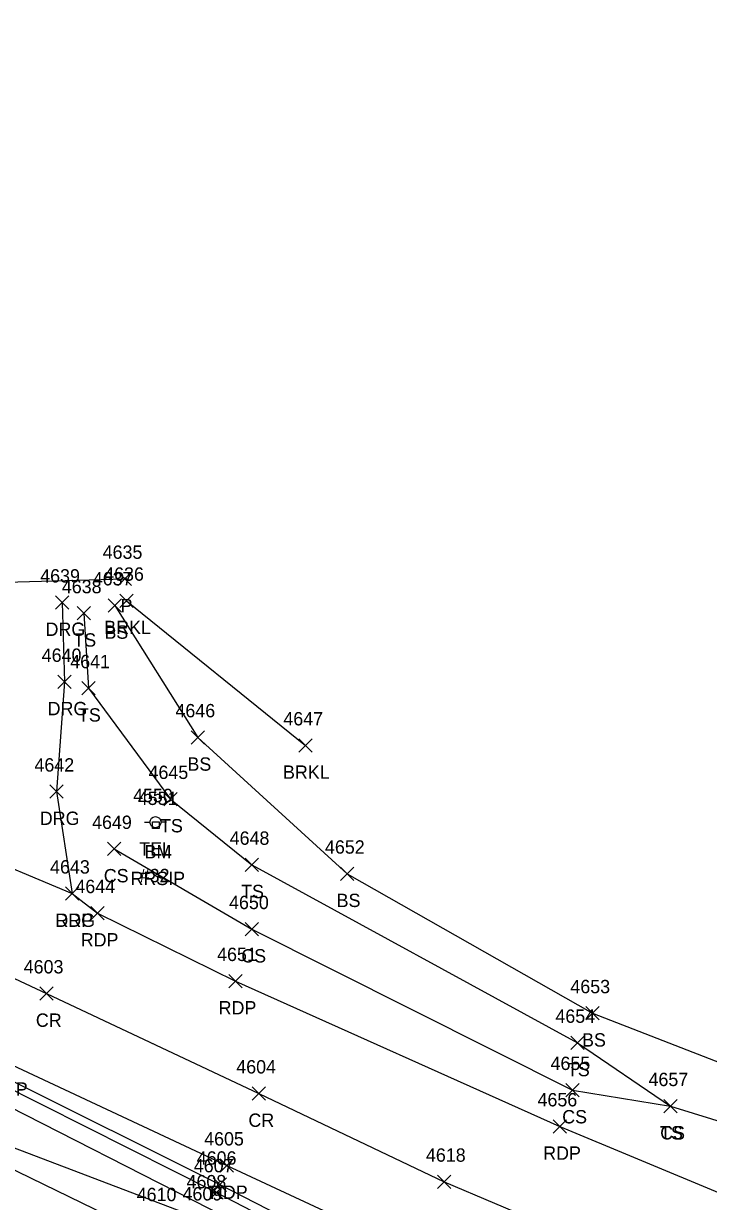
# Model space of a CAD drawing. Extents: x 1611797 to 1633212, y 298978 to 305475.
# Drawn here: x 1619703.4 to 1619805.9, y 301313.3 to 301489.8 of the extents above; entities that cross this region are included whole.
import ezdxf

# ---------------------------------------------------------------- set-up
doc = ezdxf.new("R2010")
doc.units = 0
for name, color, linetype in [('C_A', 7, 'Continuous'), ('C_C', 7, 'Continuous'), ('C_I', 7, 'Continuous'), ('CPBM', 7, 'Continuous'), ('D_A', 7, 'Continuous'), ('D_I', 7, 'Continuous'), ('D_TIC', 7, 'Continuous'), ('DCP', 7, 'Continuous'), ('L_A', 7, 'Continuous'), ('L_I', 7, 'Continuous'), ('L_TIC', 7, 'Continuous'), ('LAWA', 7, 'Continuous'), ('LAWE', 7, 'Continuous'), ('LELB', 7, 'Continuous'), ('M_I', 7, 'Continuous'), ('P_A', 7, 'Continuous'), ('P_I', 7, 'Continuous'), ('P_TIC', 7, 'Continuous'), ('PET', 7, 'Continuous'), ('PRC', 7, 'Continuous'), ('R_A', 7, 'Continuous'), ('R_I', 7, 'Continuous'), ('R_TIC', 7, 'Continuous'), ('RDG', 7, 'Continuous'), ('U_A', 7, 'Continuous'), ('U_C', 7, 'Continuous'), ('U_I', 7, 'Continuous'), ('UP', 7, 'Continuous')]:
    doc.layers.add(name, color=color, linetype=linetype)

msp = doc.modelspace()

# ---------------------------------------------------------------- linework, layer by layer
at = {"layer": 'CPBM'}
for p, q in [((1619722.68, 301369.21), (1619722.68, 301370.21)), ((1619722.68, 301370.21), (1619723.68, 301370.21)), ((1619723.68, 301370.21), (1619723.68, 301369.21)), ((1619723.68, 301369.21), (1619722.68, 301369.21)), ((1619723.18, 301369.71), (1619723.18, 301369.71)), ((1619723.18, 301369.71), (1619723.18, 301369.71))]:
    msp.add_line(p, q, dxfattribs=at)
at = {"layer": 'D_TIC'}
for points in [[(1619717.54, 301405.6), (1619719.54, 301407.6)], [(1619719.54, 301405.6), (1619717.54, 301407.6)]]:
    msp.add_lwpolyline(points, dxfattribs=at)
at = {"layer": 'DCP'}
msp.add_lwpolyline([(1619688.22, 301405.73), (1619718.54, 301406.6)], dxfattribs=at)
at = {"layer": 'L_TIC'}
for points in [[(1619716.05, 301401.62), (1619718.05, 301403.62)], [(1619718.05, 301401.62), (1619716.05, 301403.62)], [(1619717.82, 301402.32), (1619719.82, 301404.32)], [(1619719.82, 301402.32), (1619717.82, 301404.32)], [(1619711.43, 301400.44), (1619713.43, 301402.44)], [(1619713.43, 301400.44), (1619711.43, 301402.44)], [(1619712.12, 301389.21), (1619714.12, 301391.21)], [(1619714.12, 301389.21), (1619712.12, 301391.21)], [(1619728.49, 301381.85), (1619730.49, 301383.85)], [(1619730.49, 301381.85), (1619728.49, 301383.85)], [(1619744.59, 301380.64), (1619746.59, 301382.64)], [(1619746.59, 301380.64), (1619744.59, 301382.64)], [(1619724.41, 301372.61), (1619726.41, 301374.61)], [(1619726.41, 301372.61), (1619724.41, 301374.61)], [(1619715.96, 301365.12), (1619717.96, 301367.12)], [(1619717.96, 301365.12), (1619715.96, 301367.12)], [(1619736.56, 301362.75), (1619738.56, 301364.75)], [(1619738.56, 301362.75), (1619736.56, 301364.75)], [(1619750.83, 301361.42), (1619752.83, 301363.42)], [(1619752.83, 301361.42), (1619750.83, 301363.42)], [(1619736.55, 301353.11), (1619738.55, 301355.11)], [(1619738.55, 301353.11), (1619736.55, 301355.11)], [(1619787.58, 301340.51), (1619789.58, 301342.51)], [(1619789.58, 301340.51), (1619787.58, 301342.51)], [(1619785.34, 301336.07), (1619787.34, 301338.07)], [(1619787.34, 301336.07), (1619785.34, 301338.07)], [(1619784.6, 301329), (1619786.6, 301331)], [(1619786.6, 301329), (1619784.6, 301331)], [(1619799.28, 301326.59), (1619801.28, 301328.59)], [(1619801.28, 301326.59), (1619799.28, 301328.59)], [(1619799.28, 301326.59), (1619801.28, 301328.59)], [(1619801.28, 301326.59), (1619799.28, 301328.59)], [(1619731.26, 301313.67), (1619733.26, 301315.67)], [(1619733.26, 301313.67), (1619731.26, 301315.67)], [(1619731.76, 301314.82), (1619733.76, 301316.82)], [(1619733.76, 301314.82), (1619731.76, 301316.82)]]:
    msp.add_lwpolyline(points, dxfattribs=at)
at = {"layer": 'LAWA'}
msp.add_lwpolyline([(1619507.86, 301398.95), (1619518.08, 301400.79), (1619556.65, 301387.52), (1619583.35, 301368.71), (1619617.87, 301352.68), (1619658.72, 301335.08), (1619694.86, 301321.5), (1619725.46, 301306.6), (1619750.78, 301288.01), (1619784.9, 301274.32), (1619812.4, 301257.15), (1619844.1, 301250.77), (1619874.95, 301250.41), (1619914.22, 301239.23), (1619945.35, 301230.93), (1619986.13, 301221.13), (1620021.48, 301214.73), (1620067.45, 301208.49), (1620101.58, 301197.67), (1620125.21, 301192.85)], dxfattribs=at)
at = {"layer": 'LAWE'}
msp.add_lwpolyline([(1619718.82, 301403.32), (1619745.59, 301381.64)], dxfattribs=at)
at = {"layer": 'LELB'}
for points in [[(1619350.31, 301489.81), (1619380.89, 301476.99), (1619406.21, 301465.78), (1619425.96, 301458.32), (1619457.01, 301443.93), (1619488.18, 301429.04), (1619515.79, 301415.84), (1619523.25, 301412.34), (1619557.22, 301396.43), (1619595.64, 301379.74), (1619625.49, 301366.11), (1619664.9, 301348.53), (1619700.1, 301332.19), (1619732.76, 301315.82), (1619759.48, 301302.13), (1619789.83, 301287.62), (1619820.2, 301275.83), (1619850.42, 301266.87), (1619878.56, 301257.32), (1619912.05, 301251.69), (1619947.78, 301244.54), (1619986.64, 301235.92)], [(1619515.86, 301413.84), (1619522.39, 301411.67), (1619557.04, 301395.57), (1619595.01, 301378.34), (1619625.28, 301365.19), (1619664.7, 301347.42), (1619699.56, 301331.11), (1619732.26, 301314.67), (1619758.81, 301300.85), (1619789.23, 301285.42), (1619819.18, 301274.31), (1619849.56, 301265.07), (1619878.74, 301254.24), (1619911.39, 301248.67), (1619947.63, 301242.31), (1619986.12, 301232.79)], [(1619514.13, 301412.04), (1619521.16, 301409.66), (1619556.07, 301393.79), (1619593.93, 301376.98), (1619624.81, 301363.73), (1619664.19, 301346.3), (1619698.66, 301328.84), (1619731.18, 301312.27), (1619757.56, 301299.07), (1619788.59, 301282.92), (1619818.22, 301271.64), (1619848.03, 301261.72), (1619876.44, 301251.78), (1619910.7, 301243.48), (1619946.63, 301234.74), (1619971.5, 301227.31), (1619985.16, 301225.14), (1620021.48, 301214.73)], [(1619717.05, 301402.62), (1619729.49, 301382.85), (1619751.83, 301362.42), (1619788.58, 301341.51), (1619840.33, 301321.37), (1619859.82, 301312.4), (1619885.93, 301308.98), (1619917.76, 301301.6), (1619954.63, 301284.39), (1619995.46, 301278.81), (1620037.59, 301270.1), (1620080.58, 301262.9), (1620111.05, 301256.31), (1620134.36, 301250.9), (1620155.92, 301243.69), (1620184.2, 301240.01), (1620186.37, 301239.29), (1620187.23, 301238.52), (1620209.89, 301239.08), (1620216.8, 301243.54), (1620236.7, 301237.64)], [(1619712.43, 301401.44), (1619713.12, 301390.21), (1619725.41, 301373.61), (1619737.56, 301363.75), (1619786.34, 301337.07), (1619800.28, 301327.59), (1619837.75, 301316), (1619857.62, 301306.82), (1619872.16, 301301.99), (1619887.37, 301302.9), (1619915.15, 301296.19), (1619953.85, 301281.7), (1619995.44, 301273.48), (1620035.7, 301263.81), (1620079.78, 301255.69), (1620110.34, 301250.13), (1620133.61, 301245.85), (1620185.9, 301234.31), (1620209.46, 301228.92), (1620249.02, 301218.59), (1620282.74, 301209.51), (1620314.25, 301201.24), (1620350.31, 301189.61), (1620412.81, 301166.44)], [(1619716.96, 301366.12), (1619737.55, 301354.11), (1619785.6, 301330), (1619800.28, 301327.59)], [(1619685.12, 301328.75), (1619696.06, 301323.61), (1619730.59, 301310.45), (1619756.56, 301297.34), (1619787.5, 301280.33), (1619817.39, 301268.62), (1619845.61, 301256.67), (1619874.95, 301250.41)]]:
    msp.add_lwpolyline(points, dxfattribs=at)
at = {"layer": 'P_TIC'}
for points in [[(1619709.67, 301358.44), (1619711.67, 301360.44)], [(1619711.67, 301358.44), (1619709.67, 301360.44)], [(1619713.46, 301355.51), (1619715.46, 301357.51)], [(1619715.46, 301355.51), (1619713.46, 301357.51)], [(1619734.11, 301345.33), (1619736.11, 301347.33)], [(1619736.11, 301345.33), (1619734.11, 301347.33)], [(1619705.8, 301343.47), (1619707.8, 301345.47)], [(1619707.8, 301343.47), (1619705.8, 301345.47)], [(1619737.62, 301328.48), (1619739.62, 301330.48)], [(1619739.62, 301328.48), (1619737.62, 301330.48)], [(1619782.71, 301323.55), (1619784.71, 301325.55)], [(1619784.71, 301323.55), (1619782.71, 301325.55)], [(1619732.81, 301317.69), (1619734.81, 301319.69)], [(1619734.81, 301317.69), (1619732.81, 301319.69)], [(1619765.38, 301315.26), (1619767.38, 301317.26)], [(1619767.38, 301315.26), (1619765.38, 301317.26)]]:
    msp.add_lwpolyline(points, dxfattribs=at)
at = {"layer": 'PET'}
for points in [[(1619561.18, 301427.13), (1619589.22, 301414.46), (1619621.64, 301399.56), (1619645.53, 301388.44), (1619676.08, 301374.23), (1619678.71, 301373.41), (1619694.71, 301366.12), (1619710.67, 301359.44), (1619714.46, 301356.51), (1619735.11, 301346.33), (1619783.71, 301324.55), (1619832.02, 301304.42), (1619849.55, 301298.27), (1619870.41, 301291.84), (1619910.7, 301281.21), (1619950.83, 301272.88), (1619994.49, 301265.52)], [(1619558.04, 301399.85), (1619596.27, 301382.3), (1619626.79, 301368.76), (1619665.72, 301350.73), (1619700.87, 301334.15), (1619733.81, 301318.69), (1619761.36, 301305.85), (1619791.6, 301292.8), (1619823.48, 301280.05), (1619851.63, 301270.31), (1619880.36, 301262.32), (1619912.48, 301254.3), (1619949.02, 301246.88), (1619987.97, 301240.43)]]:
    msp.add_lwpolyline(points, dxfattribs=at)
at = {"layer": 'PRC'}
msp.add_lwpolyline([(1619561.88, 301411.99), (1619599.81, 301394.69), (1619632.15, 301379.47), (1619669.86, 301361.78), (1619706.8, 301344.47), (1619738.62, 301329.48), (1619766.38, 301316.26), (1619796.53, 301303.45), (1619827.59, 301291.15), (1619854.63, 301281.96), (1619882.39, 301274.22), (1619915.66, 301266.28), (1619950.93, 301259.45), (1619990.95, 301252.78)], dxfattribs=at)
at = {"layer": 'R_TIC'}
for points in [[(1619708.19, 301402.05), (1619710.19, 301404.05)], [(1619710.19, 301402.05), (1619708.19, 301404.05)], [(1619708.5, 301390.16), (1619710.5, 301392.16)], [(1619710.5, 301390.16), (1619708.5, 301392.16)], [(1619707.33, 301373.72), (1619709.33, 301375.72)], [(1619709.33, 301373.72), (1619707.33, 301375.72)], [(1619709.67, 301358.44), (1619711.67, 301360.44)], [(1619711.67, 301358.44), (1619709.67, 301360.44)]]:
    msp.add_lwpolyline(points, dxfattribs=at)
at = {"layer": 'RDG'}
msp.add_lwpolyline([(1619709.19, 301403.05), (1619709.5, 301391.16), (1619708.33, 301374.72), (1619710.67, 301359.44)], dxfattribs=at)
at = {"layer": 'UP'}
for p, q in [((1619721.48, 301370.13), (1619722.3, 301370.13)), ((1619723.14, 301370.14), (1619723.14, 301370.14)), ((1619724.8, 301370.14), (1619723.97, 301370.14)), ((1619723.97, 301370.14), (1619723.97, 301370.14)), ((1619724.8, 301370.14), (1619724.8, 301370.14))]:
    msp.add_line(p, q, dxfattribs=at)
msp.add_circle((1619723.14, 301370.14), 0.833, dxfattribs=at)

# ---------------------------------------------------------------- texts
at = {"layer": 'C_A'}
msp.add_text('BM', height=2, dxfattribs=at).set_placement((1619721.5, 301364.71))
at = {"layer": 'C_C'}
msp.add_text('RRSIP', height=2, dxfattribs=at).set_placement((1619719.4, 301360.71))
at = {"layer": 'C_I'}
msp.add_text('4551', height=2, dxfattribs=at).set_placement((1619720.49, 301372.71))
at = {"layer": 'D_A'}
msp.add_text('P', height=2, dxfattribs=at).set_placement((1619717.91, 301401.6))
at = {"layer": 'D_I'}
msp.add_text('4635', height=2, dxfattribs=at).set_placement((1619715.23, 301409.6))
at = {"layer": 'L_A'}
for s, p in [('BRKL', (1619715.47, 301398.32)), ('TS', (1619710.84, 301396.44)), ('BS', (1619715.49, 301397.62)), ('TS', (1619711.53, 301385.21)), ('BS', (1619727.93, 301377.85)), ('BRKL', (1619742.24, 301376.64)), ('TS', (1619723.82, 301368.61)), ('CS', (1619715.4, 301361.12)), ('TS', (1619735.97, 301358.75)), ('BS', (1619750.27, 301357.42)), ('CS', (1619735.99, 301349.11)), ('BS', (1619787.02, 301336.51)), ('TS', (1619784.75, 301332.07)), ('CS', (1619784.05, 301325)), ('TS', (1619798.69, 301322.59)), ('CS', (1619798.72, 301322.59))]:
    msp.add_text(s, height=2, dxfattribs=at).set_placement(p)
at = {"layer": 'L_I'}
for s, p in [('4637', (1619713.75, 301405.62)), ('4636', (1619715.46, 301406.32)), ('4638', (1619709.12, 301404.44)), ('4641', (1619710.38, 301393.21)), ('4646', (1619726.13, 301385.85)), ('4647', (1619742.29, 301384.64)), ('4645', (1619722.1, 301376.61)), ('4649', (1619713.65, 301369.12)), ('4648', (1619734.25, 301366.75)), ('4652', (1619748.52, 301365.42)), ('4650', (1619734.16, 301357.11)), ('4653', (1619785.27, 301344.51)), ('4654', (1619783.03, 301340.07)), ('4655', (1619782.3, 301333)), ('4657', (1619796.97, 301330.59)), ('4657', (1619796.97, 301330.59)), ('4606', (1619729.32, 301318.82)), ('4607', (1619728.88, 301317.67)), ('4608', (1619727.79, 301315.27)), ('4609', (1619727.19, 301313.45))]:
    msp.add_text(s, height=2, dxfattribs=at).set_placement(p)
at = {"layer": 'M_I'}
msp.add_text('4610', height=2, dxfattribs=at).set_placement((1619720.33, 301313.35))
at = {"layer": 'P_A'}
for s, p in [('RDP', (1619708.15, 301354.44)), ('RDP', (1619711.95, 301351.51)), ('RDP', (1619732.6, 301341.33)), ('CR', (1619705.23, 301339.47)), ('RDP', (1619698.36, 301329.15)), ('CR', (1619737.06, 301324.48)), ('RDP', (1619781.2, 301319.55)), ('RDP', (1619731.3, 301313.69))]:
    msp.add_text(s, height=2, dxfattribs=at).set_placement(p)
at = {"layer": 'P_I'}
for s, p in [('4643', (1619707.36, 301362.44)), ('4644', (1619711.15, 301359.51)), ('4651', (1619732.37, 301349.33)), ('4603', (1619703.41, 301347.47)), ('4604', (1619735.24, 301332.48)), ('4656', (1619780.35, 301327.55)), ('4605', (1619730.43, 301321.69)), ('4618', (1619763.64, 301319.26))]:
    msp.add_text(s, height=2, dxfattribs=at).set_placement(p)
at = {"layer": 'R_A'}
for p in [(1619706.68, 301398.05), (1619706.99, 301386.16), (1619705.82, 301369.72), (1619708.15, 301354.44)]:
    msp.add_text('DRG', height=2, dxfattribs=at).set_placement(p)
at = {"layer": 'R_I'}
for s, p in [('4639', (1619705.88, 301406.05)), ('4640', (1619706.11, 301394.16)), ('4642', (1619705.02, 301377.72)), ('4643', (1619707.36, 301362.44))]:
    msp.add_text(s, height=2, dxfattribs=at).set_placement(p)
at = {"layer": 'U_A'}
msp.add_text('TEL', height=2, dxfattribs=at).set_placement((1619720.7, 301365.14))
at = {"layer": 'U_C'}
msp.add_text('#32', height=2, dxfattribs=at).set_placement((1619720.78, 301361.14))
at = {"layer": 'U_I'}
msp.add_text('4550', height=2, dxfattribs=at).set_placement((1619719.79, 301373.14))

doc.saveas('drawing.dxf')
